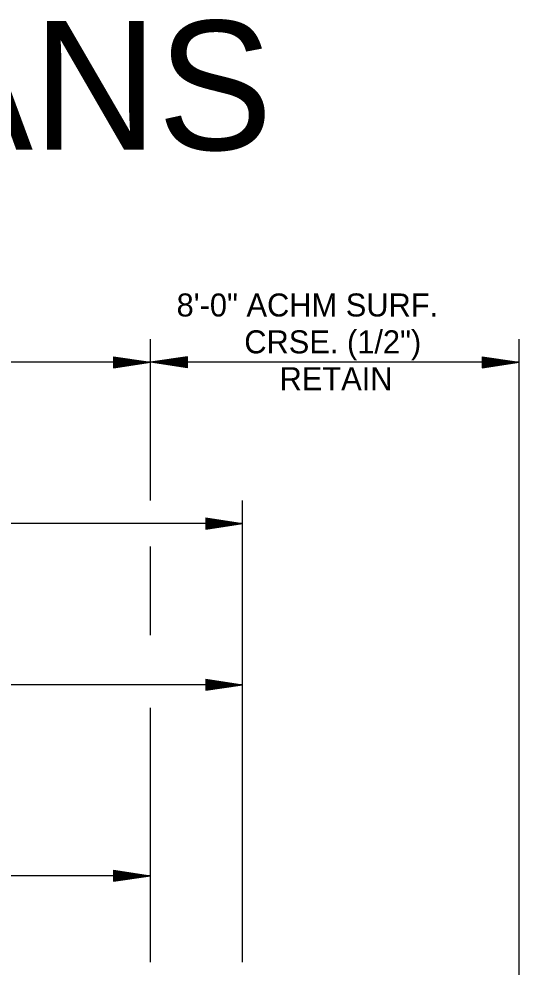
# Model space of a CAD drawing. Extents: x 60325 to 61047, y 53669 to 53767.
# Drawn here: x 60378.39 to 60389.25, y 53746.21 to 53766.8 of the extents above; entities that cross this region are included whole.
import ezdxf

# ---------------------------------------------------------------- set-up
doc = ezdxf.new("R2010")
doc.units = 0
for name, color, linetype in [('Level 63', 7, 'Continuous'), ('R_Border', 7, 'Continuous'), ('R_Border Prem', 7, 'Continuous')]:
    doc.layers.add(name, color=color, linetype=linetype)

msp = doc.modelspace()

# ---------------------------------------------------------------- linework, layer by layer
at = {"layer": 'R_Border'}
for p, q in [((60381.247, 53746.323), (60381.247, 53748.874)), ((60380.447, 53748.318), (60381.247, 53748.198)), ((60380.447, 53748.318), (60380.447, 53748.078)), ((60380.447, 53748.298), (60381.113, 53748.198)), ((60380.447, 53748.277), (60380.975, 53748.198)), ((60380.447, 53748.257), (60380.842, 53748.198)), ((60381.247, 53748.198), (60353.247, 53748.198)), ((60380.447, 53748.237), (60380.707, 53748.198)), ((60380.447, 53748.217), (60380.573, 53748.198)), ((60380.447, 53748.078), (60381.247, 53748.198)), ((60380.447, 53748.159), (60380.707, 53748.198)), ((60380.447, 53748.118), (60380.975, 53748.198)), ((60380.447, 53748.098), (60381.113, 53748.198)), ((60380.447, 53748.138), (60380.842, 53748.198)), ((60380.447, 53748.179), (60380.573, 53748.198))]:
    msp.add_line(p, q, dxfattribs=at)
at = {"layer": 'R_Border Prem'}
for p, q in [((60381.247, 53756.345), (60381.247, 53759.845)), ((60389.247, 53746.595), (60389.247, 53759.845)), ((60380.447, 53759.465), (60381.247, 53759.345)), ((60380.447, 53759.465), (60380.447, 53759.225)), ((60380.447, 53759.445), (60381.113, 53759.345)), ((60380.447, 53759.424), (60380.975, 53759.345)), ((60380.447, 53759.404), (60380.842, 53759.345)), ((60380.447, 53759.383), (60380.707, 53759.345)), ((60380.447, 53759.363), (60380.573, 53759.345)), ((60382.047, 53759.465), (60381.247, 53759.345)), ((60382.047, 53759.445), (60381.38, 53759.345)), ((60382.047, 53759.424), (60381.518, 53759.345)), ((60382.047, 53759.404), (60381.651, 53759.345)), ((60382.047, 53759.384), (60381.787, 53759.345)), ((60382.047, 53759.363), (60381.92, 53759.345)), ((60382.047, 53759.225), (60382.047, 53759.465)), ((60388.447, 53759.465), (60389.247, 53759.345)), ((60388.447, 53759.465), (60388.447, 53759.225)), ((60388.447, 53759.445), (60389.113, 53759.345)), ((60388.447, 53759.424), (60388.975, 53759.345)), ((60388.447, 53759.404), (60388.842, 53759.345)), ((60388.447, 53759.383), (60388.707, 53759.345)), ((60388.447, 53759.363), (60388.573, 53759.345)), ((60381.247, 53759.345), (60353.247, 53759.345)), ((60380.447, 53759.225), (60381.247, 53759.345)), ((60380.447, 53759.305), (60380.707, 53759.345)), ((60380.447, 53759.265), (60380.975, 53759.345)), ((60380.447, 53759.245), (60381.113, 53759.345)), ((60380.447, 53759.285), (60380.842, 53759.345)), ((60380.447, 53759.326), (60380.573, 53759.345)), ((60389.247, 53759.345), (60381.247, 53759.345)), ((60382.047, 53759.225), (60381.247, 53759.345)), ((60382.047, 53759.245), (60381.38, 53759.345)), ((60382.047, 53759.265), (60381.518, 53759.345)), ((60382.047, 53759.285), (60381.651, 53759.345)), ((60382.047, 53759.306), (60381.787, 53759.345)), ((60382.047, 53759.326), (60381.92, 53759.345)), ((60388.447, 53759.225), (60389.247, 53759.345)), ((60388.447, 53759.305), (60388.707, 53759.345)), ((60388.447, 53759.265), (60388.975, 53759.345)), ((60388.447, 53759.245), (60389.113, 53759.345)), ((60388.447, 53759.285), (60388.842, 53759.345)), ((60388.447, 53759.326), (60388.573, 53759.345)), ((60383.247, 53746.323), (60383.247, 53756.345)), ((60382.447, 53755.965), (60383.247, 53755.845)), ((60382.447, 53755.965), (60382.447, 53755.725)), ((60382.447, 53755.945), (60383.113, 53755.845)), ((60382.447, 53755.924), (60382.975, 53755.845)), ((60382.447, 53755.904), (60382.842, 53755.845)), ((60382.447, 53755.883), (60382.707, 53755.845)), ((60382.447, 53755.863), (60382.573, 53755.845)), ((60383.247, 53755.845), (60351.247, 53755.845)), ((60382.447, 53755.725), (60383.247, 53755.845)), ((60382.447, 53755.805), (60382.707, 53755.845)), ((60382.447, 53755.765), (60382.975, 53755.845)), ((60382.447, 53755.745), (60383.113, 53755.845)), ((60382.447, 53755.785), (60382.842, 53755.845)), ((60382.447, 53755.826), (60382.573, 53755.845)), ((60381.247, 53753.422), (60381.247, 53755.345)), ((60382.447, 53752.465), (60383.247, 53752.345)), ((60382.447, 53752.465), (60382.447, 53752.225)), ((60382.447, 53752.445), (60383.113, 53752.345)), ((60382.447, 53752.424), (60382.975, 53752.345)), ((60382.447, 53752.404), (60382.842, 53752.345)), ((60382.447, 53752.383), (60382.707, 53752.345)), ((60382.447, 53752.363), (60382.573, 53752.345)), ((60383.247, 53752.345), (60353.247, 53752.345)), ((60382.447, 53752.225), (60383.247, 53752.345)), ((60382.447, 53752.305), (60382.707, 53752.345)), ((60382.447, 53752.265), (60382.975, 53752.345)), ((60382.447, 53752.245), (60383.113, 53752.345)), ((60382.447, 53752.285), (60382.842, 53752.345)), ((60382.447, 53752.326), (60382.573, 53752.345)), ((60381.247, 53748.874), (60381.247, 53751.845)), ((60389.247, 53741.005), (60389.247, 53746.595))]:
    msp.add_line(p, q, dxfattribs=at)

# ---------------------------------------------------------------- texts
at = {"layer": 'Level 63'}
msp.add_text('FROM CA0904 PLANS', height=2.8, dxfattribs=at).set_placement((60344.986, 53763.958))
at = {"layer": 'R_Border Prem'}
for s, p in [('8\'-0" ACHM SURF.', (60381.814, 53760.339)), ('CRSE. (1/2")', (60383.283, 53759.539)), ('RETAIN', (60384.049, 53758.739))]:
    msp.add_text(s, height=0.5, dxfattribs=at).set_placement(p)

doc.saveas('drawing.dxf')
